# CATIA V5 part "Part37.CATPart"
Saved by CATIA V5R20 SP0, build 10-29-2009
Part number: VA 161320-6_Circlip DIN 471 - 5 x 0.6
Revision: ANY
Definition: UNKNOWN
Nomenclature: VA 161320-6_Circlip DIN 471 - 5 x 0.6
Source: Unknown
Bounding box of the stored display mesh (mm): x -3.167 to 3.167, y -4.898 to 3.345, z -0.6 to 0
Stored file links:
  C:\Users\Utente\Desktop\IO LAVORO\3D X SITO CF\CUMSA\3D files VA\VA 201720\Part37.CATPart
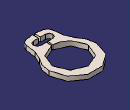
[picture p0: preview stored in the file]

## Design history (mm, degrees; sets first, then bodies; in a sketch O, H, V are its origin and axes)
Body1 "Notch" (main body)
  Solid1: solid without history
